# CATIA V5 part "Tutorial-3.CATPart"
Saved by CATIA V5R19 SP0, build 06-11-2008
Part number: c03tut3
Bounding box of the stored display mesh (mm): x 0 to 0, y -100 to 100, z 0 to 90
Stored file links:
  D:\Shriniwas\v5_r19\Part files\c03\c03tut3.CATPart
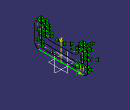
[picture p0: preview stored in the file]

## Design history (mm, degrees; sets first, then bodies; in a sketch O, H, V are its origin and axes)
Body1 (main body)
  Sketch1 on yz-plane, origin (0, 0, 0), H (0, 1, 0), V (0, 0, 1)
    line L1 (0, 0) -> (85, 0)
    line L2 (100, 15) -> (100, 80)
    line L3 (90, 90) -> (70, 90)
    line L4 (60, 80) -> (60, 60)
    line L5 (50, 50) -> (0, 50)
    point P1 (0, 50)
    arc A1 centre (85, 15) radius 15 from (85, 0) to (100, 15) ccw
    point P2 (85, 0)
    point P3 (100, 15)
    arc A2 centre (50, 60) radius 10 from (60, 60) to (50, 50) cw
    point P5 (60, 60)
    point P6 (50, 50)
    arc A3 centre (70, 80) radius 10 from (70, 90) to (60, 80) ccw
    point P8 (70, 90)
    point P9 (60, 80)
    arc A4 centre (90, 80) radius 10 from (100, 80) to (90, 90) ccw
    point P11 (100, 80)
    point P12 (90, 90)
    construction line L6 (80, 70) -> (80, 40)
    line L7 (85, 70) -> (85, 40)
    line L8 (75, 40) -> (75, 70)
    arc A5 centre (80, 40) radius 5 from (85, 40) to (75, 40) cw
    arc A6 centre (80, 70) radius 5 from (75, 70) to (85, 70) cw
    point P16 (85, 70)
    point P17 (85, 40)
    point P18 (75, 40)
    point P19 (75, 70)
    point P20 (0, 0)
    point P21 (0, 50)
    point P22 (-85, 0)
    point P23 (-100, 15)
    point P25 (-60, 60)
    point P26 (-50, 50)
    point P28 (-70, 90)
    point P29 (-60, 80)
    point P31 (-100, 80)
    point P32 (-90, 90)
    construction line L9 (-80, 70) -> (-80, 40)
    point P36 (-85, 70)
    point P37 (-85, 40)
    point P38 (-75, 40)
    point P39 (-75, 70)
    line L10 (0, 0) -> (-85, 0)
    line L11 (-100, 15) -> (-100, 80)
    line L12 (-90, 90) -> (-70, 90)
    line L13 (-60, 80) -> (-60, 60)
    line L14 (-50, 50) -> (0, 50)
    arc A7 centre (-85, 15) radius 15 from (-85, 0) to (-100, 15) cw
    arc A8 centre (-50, 60) radius 10 from (-60, 60) to (-50, 50) ccw
    arc A9 centre (-70, 80) radius 10 from (-70, 90) to (-60, 80) cw
    arc A10 centre (-90, 80) radius 10 from (-100, 80) to (-90, 90) cw
    line L15 (-85, 70) -> (-85, 40)
    line L16 (-75, 40) -> (-75, 70)
    arc A11 centre (-80, 40) radius 5 from (-85, 40) to (-75, 40) ccw
    arc A12 centre (-80, 70) radius 5 from (-75, 70) to (-85, 70) ccw
    construction line L17 (60, 20) -> (-60, 20)
    point P40 (60, 20)
    line L18 (60, 10) -> (-60, 10)
    line L19 (-60, 30) -> (60, 30)
    arc A13 centre (-60, 20) radius 10 from (-60, 10) to (-60, 30) cw
    arc A14 centre (60, 20) radius 10 from (60, 30) to (60, 10) cw
    radius A1 = 15
    radius A2 = 10
    radius A3 = 10
    radius A4 = 10
    distance L6 L7 = 5
    distance L17 L18 = 10
    horizontal: L1 H, L3 H, L5 H, L17 H
    vertical: L2 V, L4 V
    coincidence: P1 V, P40 L4
    tangency: A1 L1, A1 L2, A2 L4, A2 L5, A3 L3, A3 L4, A4 L2, A4 L3, L6 A3, A5 L7, A6 L7, A5 L8, A6 L8, A13 L18, A14 L18, A13 L19, A14 L19
    symmetry: O P20 V, P1 P21 V, P2 P22 V, P3 P23 V, P5 P25 V, P6 P26 V, P8 P28 V, P9 P29 V, P11 P31 V, P12 P32 V, L6 L9 V, P16 P36 V, P17 P37 V, P18 P38 V, P19 P39 V, L1 L10 V, L2 L11 V, L3 L12 V, L4 L13 V, L5 L14 V, A1 A7 V, A2 A8 V, A3 A9 V, A4 A10 V, L7 L15 V, L8 L16 V, A5 A11 V, A6 A12 V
